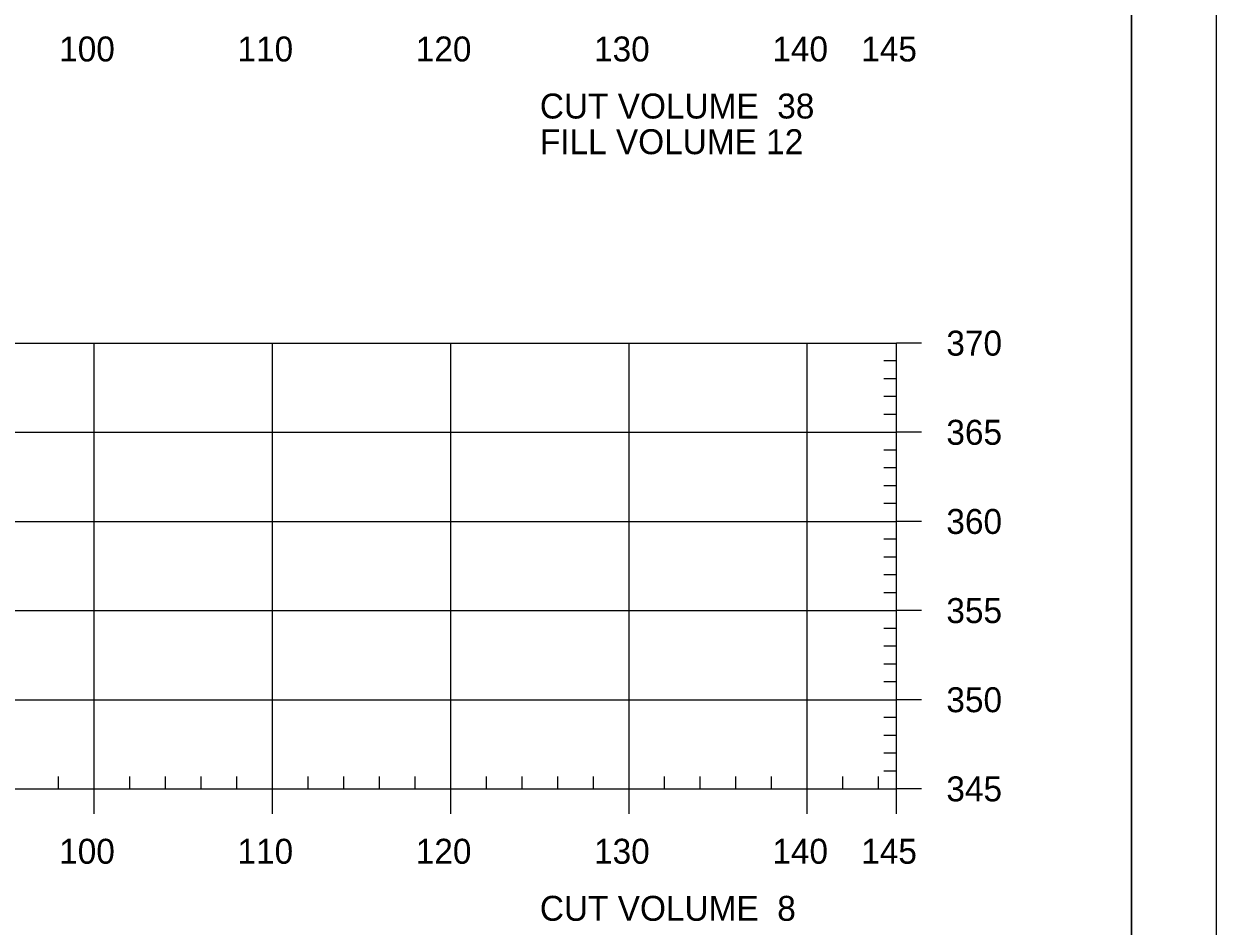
# Model space of a CAD drawing. Extents: x 1359801 to 1362404, y 372415 to 374228.
# Drawn here: x 1360067.4 to 1360134.3, y 373268.6 to 373319.2 of the extents above; entities that cross this region are included whole.
import ezdxf

# ---------------------------------------------------------------- set-up
doc = ezdxf.new("R2010")
doc.units = 0
for name, color, linetype in [('S_MAILBOX', 7, 'Continuous'), ('S_PRIMARY_CTL', 7, 'Continuous'), ('S_SHOULDER', 7, 'Continuous'), ('S_UTL_PT_SYM', 7, 'Continuous'), ('S_WATER_UTILITIES', 7, 'Continuous')]:
    doc.layers.add(name, color=color, linetype=linetype)

msp = doc.modelspace()

# ---------------------------------------------------------------- linework, layer by layer
at = {"layer": 'S_MAILBOX'}
for p, q in [((1359826.35, 373301.26), (1360116.35, 373301.26)), ((1360071.35, 373276.26), (1360071.35, 373301.26)), ((1360081.35, 373276.26), (1360081.35, 373301.26)), ((1360091.35, 373276.26), (1360091.35, 373301.26)), ((1360101.35, 373276.26), (1360101.35, 373301.26)), ((1360111.35, 373276.26), (1360111.35, 373301.26)), ((1360116.35, 373276.26), (1360116.35, 373301.26)), ((1359826.35, 373296.26), (1360116.35, 373296.26)), ((1359826.35, 373291.26), (1360116.35, 373291.26)), ((1359826.35, 373286.26), (1360116.35, 373286.26)), ((1359826.35, 373281.26), (1360116.35, 373281.26)), ((1359826.35, 373276.26), (1360116.35, 373276.26))]:
    msp.add_line(p, q, dxfattribs=at)
at = {"layer": 'S_SHOULDER'}
for points in [[(1359800.943, 373374.614), (1360134.283, 373374.614), (1360134.283, 373161.277), (1359800.943, 373161.277)], [(1360047.27, 373370.72), (1360047.27, 373360.84), (1360083.002, 373360.84), (1360083.002, 373357.92), (1360106.202, 373357.92), (1360106.202, 373333.587), (1360129.53, 373333.587), (1360129.53, 373165.26), (1359813.35, 373165.26), (1359813.35, 373370.72)]]:
    msp.add_lwpolyline(points, close=True, dxfattribs=at)
at = {"layer": 'S_UTL_PT_SYM'}
msp.add_line((1360129.53, 373165.26), (1360129.53, 373370.72), dxfattribs=at)
at = {"layer": 'S_WATER_UTILITIES'}
for p, q in [((1360116.35, 373276.26), (1360116.35, 373301.26)), ((1360117.75, 373301.26), (1360116.35, 373301.26)), ((1360116.35, 373300.26), (1360115.65, 373300.26)), ((1360116.35, 373299.26), (1360115.65, 373299.26)), ((1360116.35, 373298.26), (1360115.65, 373298.26)), ((1360116.35, 373297.26), (1360115.65, 373297.26)), ((1360117.75, 373296.26), (1360116.35, 373296.26)), ((1360116.35, 373295.26), (1360115.65, 373295.26)), ((1360116.35, 373294.26), (1360115.65, 373294.26)), ((1360116.35, 373293.26), (1360115.65, 373293.26)), ((1360116.35, 373292.26), (1360115.65, 373292.26)), ((1360117.75, 373291.26), (1360116.35, 373291.26)), ((1360116.35, 373290.26), (1360115.65, 373290.26)), ((1360116.35, 373289.26), (1360115.65, 373289.26)), ((1360116.35, 373288.26), (1360115.65, 373288.26)), ((1360116.35, 373287.26), (1360115.65, 373287.26)), ((1360117.75, 373286.26), (1360116.35, 373286.26)), ((1360116.35, 373285.26), (1360115.65, 373285.26)), ((1360116.35, 373284.26), (1360115.65, 373284.26)), ((1360116.35, 373283.26), (1360115.65, 373283.26)), ((1360116.35, 373282.26), (1360115.65, 373282.26)), ((1360117.75, 373281.26), (1360116.35, 373281.26)), ((1360116.35, 373280.26), (1360115.65, 373280.26)), ((1360116.35, 373279.26), (1360115.65, 373279.26)), ((1360116.35, 373278.26), (1360115.65, 373278.26)), ((1360069.35, 373276.26), (1360069.35, 373276.96)), ((1360073.35, 373276.26), (1360073.35, 373276.96)), ((1360075.35, 373276.26), (1360075.35, 373276.96)), ((1360077.35, 373276.26), (1360077.35, 373276.96)), ((1360079.35, 373276.26), (1360079.35, 373276.96)), ((1360083.35, 373276.26), (1360083.35, 373276.96)), ((1360085.35, 373276.26), (1360085.35, 373276.96)), ((1360087.35, 373276.26), (1360087.35, 373276.96)), ((1360089.35, 373276.26), (1360089.35, 373276.96)), ((1360093.35, 373276.26), (1360093.35, 373276.96)), ((1360095.35, 373276.26), (1360095.35, 373276.96)), ((1360097.35, 373276.26), (1360097.35, 373276.96)), ((1360099.35, 373276.26), (1360099.35, 373276.96)), ((1360103.35, 373276.26), (1360103.35, 373276.96)), ((1360105.35, 373276.26), (1360105.35, 373276.96)), ((1360107.35, 373276.26), (1360107.35, 373276.96)), ((1360109.35, 373276.26), (1360109.35, 373276.96)), ((1360113.35, 373276.26), (1360113.35, 373276.96)), ((1360115.35, 373276.26), (1360115.35, 373276.96)), ((1360116.35, 373277.26), (1360115.65, 373277.26)), ((1359826.35, 373276.26), (1360116.35, 373276.26)), ((1360071.35, 373274.86), (1360071.35, 373276.26)), ((1360081.35, 373274.86), (1360081.35, 373276.26)), ((1360091.35, 373274.86), (1360091.35, 373276.26)), ((1360101.35, 373274.86), (1360101.35, 373276.26)), ((1360111.35, 373274.86), (1360111.35, 373276.26)), ((1360116.35, 373274.86), (1360116.35, 373276.26)), ((1360117.75, 373276.26), (1360116.35, 373276.26))]:
    msp.add_line(p, q, dxfattribs=at)

# ---------------------------------------------------------------- texts
at = {"layer": 'S_PRIMARY_CTL'}
for s, p in [('100', (1360069.389, 373317.06)), ('110', (1360079.389, 373317.06)), ('120', (1360089.389, 373317.06)), ('130', (1360099.389, 373317.06)), ('140', (1360109.389, 373317.06)), ('145', (1360114.376, 373317.06)), ('CUT VOLUME  38', (1360096.35, 373313.86)), ('FILL VOLUME 12', (1360096.35, 373311.86)), ('370', (1360119.15, 373300.56)), ('365', (1360119.15, 373295.56)), ('360', (1360119.15, 373290.56)), ('355', (1360119.15, 373285.56)), ('350', (1360119.15, 373280.56)), ('345', (1360119.15, 373275.56)), ('100', (1360069.389, 373272.06)), ('110', (1360079.389, 373272.06)), ('120', (1360089.389, 373272.06)), ('130', (1360099.389, 373272.06)), ('140', (1360109.389, 373272.06)), ('145', (1360114.376, 373272.06)), ('CUT VOLUME  8', (1360096.35, 373268.86))]:
    msp.add_text(s, height=1.4, dxfattribs=at).set_placement(p)

doc.saveas('drawing.dxf')
